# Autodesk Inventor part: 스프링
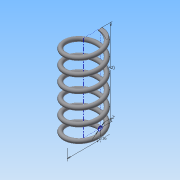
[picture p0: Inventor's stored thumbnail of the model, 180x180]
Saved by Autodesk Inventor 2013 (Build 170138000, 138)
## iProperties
Created: 2016-04
Part Number: 스프링
Material: 일반
Document SubType Name: Modeling
Designer: Administrator
Density: 1 g/cm^3
Mass: 0.936335 g
Surface Area: 18.9934 cm^2
Volume: 0.936335 cm^3
Author: Administrator
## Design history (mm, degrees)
sketch "스케치1"
  geometry: L1 (0, 0)-(8, 0); L2 (8, 0)-(8, 42); L3 (8, 42)-(0, 42); L4 (0, 42)-(0, 0); C1 r 1 at (8, 0)
  constraints: 8 end point, 2 parallel, 1 centre point, 1 coincident, 1 horizontal, 1 perpendicular
  dimensions: "d0" = 2 diameter of C1; "d2" = 16 diameter of L1.end L4; "d3" = 42 distance of L1.end L2.end (derived)
feature "코일1" sketch "스케치1" pitch "d4" = 10; turns "d6" = 6; dims "d5" = 42 (= d3), "d7" = 0, angle "d8" = 90 deg, angle "d9" = 90 deg, "d10" = 0, "d11" = 0
sketch "스케치2"
  geometry: L1 (0, 9)-(0, 7) reference; L2 (0, 9)-(0, 7) reference; 1 further point
  constraints: 2 vertical alignment
extrude "돌출1" cut sketch "스케치2" stored distance "d12" = 10; taper "d13" = 0 deg
node "작업 평면1"
sketch "스케치3"
  geometry: L1 (0, 7)-(0, 9) reference; 1 further point
  constraints: 1 vertical alignment
extrude "돌출2" cut sketch "스케치3" stored distance "d14" = 10; taper "d15" = 0 deg
node "솔리드1"
node "절단 모서리 투영1"
node "절단 모서리 투영2"
node "절단 모서리 투영3"
